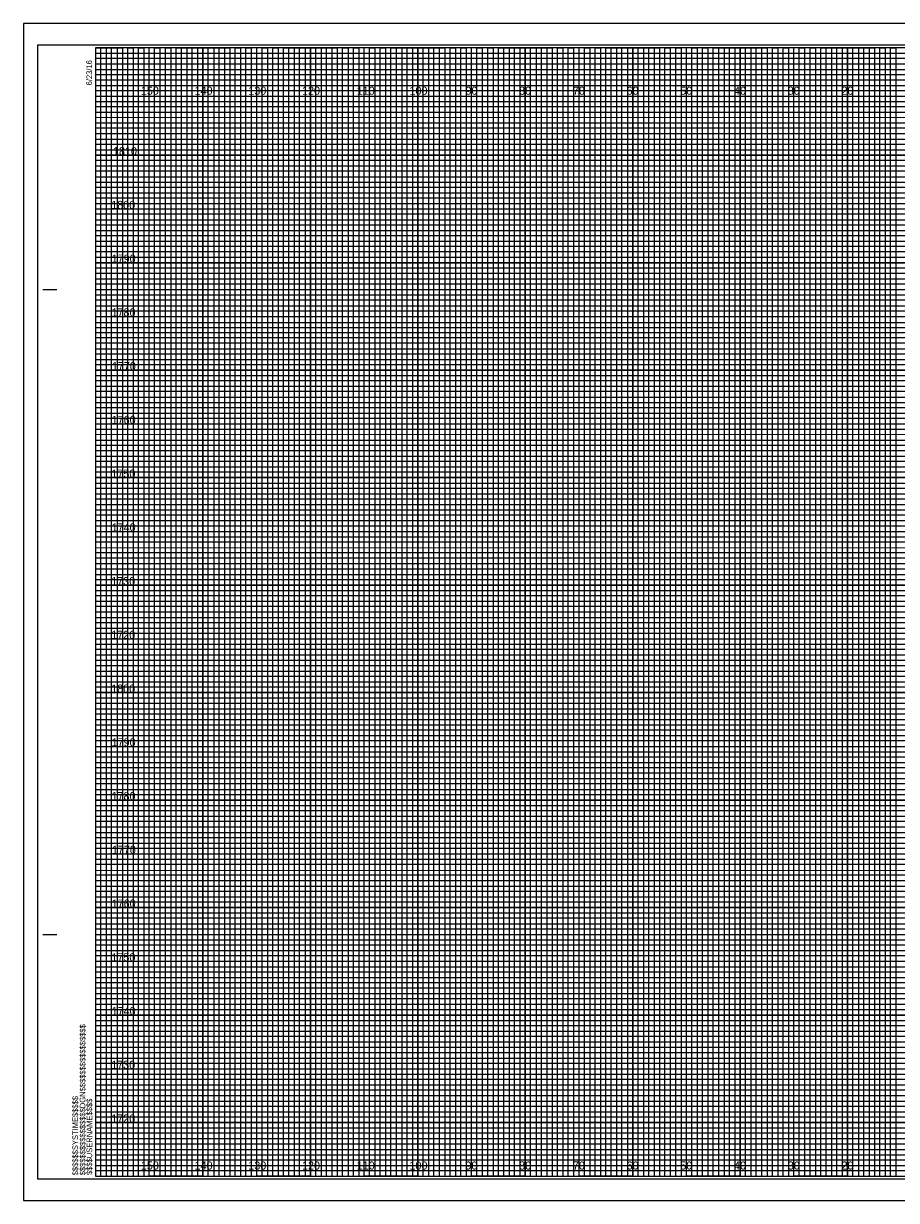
# Model space of a CAD drawing. Extents: x -13 to 323, y -5 to 874.
# Drawn here: x -13.4 to 149.1, y 655.5 to 874.5 of the extents above; entities that cross this region are included whole.
import ezdxf

# ---------------------------------------------------------------- set-up
doc = ezdxf.new("R2010")
doc.units = 0
for name, color, linetype in [('Prop XS DDE', 7, 'Continuous'), ('Prop XS DDE Elevations', 7, 'Continuous'), ('Prop XS DDE Slope Text', 7, 'Continuous'), ('Prop XS Gore Control Minimum', 7, 'Continuous'), ('Prop XS Shoulder Borrow Shape', 7, 'Continuous'), ('Raster_Level_0', 7, 'Continuous'), ('Scratch_Level_3', 7, 'Continuous'), ('Sheet Cutting Line CELL', 7, 'Continuous'), ('Sheet DOT Grid CELL', 7, 'Continuous'), ('Sheet Plot Border Inside CELL', 7, 'Continuous'), ('Sheet Plot Border Outside CELL', 7, 'Continuous')]:
    doc.layers.add(name, color=color, linetype=linetype)

msp = doc.modelspace()

# ---------------------------------------------------------------- linework, layer by layer
at = {"layer": 'Prop XS DDE'}
for p, q in [((0, 869), (260, 869)), ((260, 867.98), (0, 867.98)), ((0, 867.98), (0, 867)), ((0, 867), (260, 867)), ((260, 865.89), (0, 865.89)), ((0, 865.89), (0, 864)), ((0, 864), (320, 864))]:
    msp.add_line(p, q, dxfattribs=at)
for points in [[(0, 863), (270, 863), (320, 863), (320, 862), (0, 862)], [(0, 861), (320, 861), (320, 859), (0, 859)], [(0, 858), (320, 858), (320, 857), (0, 856.98)], [(0, 856), (320, 856), (320, 854), (0, 854)], [(0, 853), (320, 853), (320, 852), (0, 852)], [(0, 851), (320, 851), (320, 849), (0, 849)], [(0, 848), (320, 848), (320, 847), (0, 847)], [(0, 846), (320, 846), (320, 844), (0, 844)], [(0, 843), (320, 843), (320, 842), (0, 842)], [(0, 841), (320, 841), (320, 839), (0, 839)], [(0, 838), (320, 838), (320, 837), (0, 837)], [(0, 836), (320, 836), (320, 833.95), (320, 833), (320, 832), (0, 832)], [(0, 834), (320, 834), (320, 833), (0, 833)], [(0, 831), (320, 831), (320, 829), (0, 829.03)], [(0, 829.03), (320, 829), (320, 828), (0, 828)], [(0, 827), (320, 827), (320, 826), (0, 826)], [(0, 824), (320, 824), (320, 823), (0, 823)], [(0, 822), (320, 822), (320, 821), (0, 821)], [(-0.07, 818.89), (320, 818.89), (320, 817.88), (-0.07, 817.88)], [(0, 817), (320, 817), (320, 816), (0, 816)], [(0, 814), (320, 814), (320, 813), (0, 813)], [(0, 812), (320, 812), (320, 811), (0, 811)], [(0, 809), (320, 809), (320, 808), (0, 808)], [(0, 807), (320, 807), (320, 806), (0, 806)], [(0, 804), (320, 804), (320, 803), (0, 803)], [(0, 802), (320, 802), (320, 801), (0, 801)], [(0, 799), (320, 799), (319.99, 797.98), (0, 798)], [(0, 797), (320, 797), (320, 796), (0, 796)], [(0, 794), (320, 794), (320, 793), (0, 793)], [(0, 792), (320, 792), (320, 791), (0, 791)], [(0, 789), (320, 789), (320, 788), (0, 788)], [(0, 787), (320, 787), (320, 786), (0, 786)], [(0, 784), (320, 784), (320, 783), (0, 783)], [(0, 782), (320, 782), (320, 781), (0, 781)], [(0, 779), (320, 779), (320, 778), (0, 778)], [(0, 776.99), (320.07, 776.91), (320, 776), (0, 776)], [(0, 774), (320, 774), (320, 773), (0, 773)], [(0, 772), (320, 772), (320, 771), (0, 771)], [(0, 769), (320, 769), (320, 768), (0, 768)], [(0, 767), (320, 767), (320, 766), (0, 766)], [(0, 764), (320, 764), (320, 763), (0, 763)], [(0, 762), (320, 762), (320, 761), (0, 761)], [(0, 759), (320, 759), (320, 758), (0, 758)], [(0, 757), (320, 757), (320, 756), (0, 756)], [(0, 754), (320, 754), (320, 753), (0, 753)], [(0, 752), (320, 752), (320, 751), (0, 751)], [(0, 749), (320, 749), (320, 748), (0, 748)], [(0, 747), (320, 747), (320, 746), (0, 746)], [(0, 744), (320, 744), (320, 743), (0, 743)], [(0, 742), (320, 742), (320, 741), (0, 741)], [(0, 739), (320, 739), (319.99, 737.98), (0, 738)], [(0, 737), (320, 737), (320, 736), (0, 736)], [(0, 734), (320, 734), (320, 733), (0, 733)], [(0, 732), (320, 732), (320, 731), (0, 731)], [(0, 729), (320, 729), (320, 728), (0, 728)], [(0, 727), (320, 727), (320, 726), (0, 726)], [(0, 724), (320, 724), (320, 723), (0, 723)], [(0, 722), (320, 722), (320, 721), (0, 721)], [(0, 719), (320, 719), (320, 718), (0, 718)], [(0, 716.99), (320.07, 716.91), (320, 716), (0, 716)], [(0, 714), (320, 714), (320, 713), (0, 713)], [(0, 712), (320, 712), (320, 711), (0, 711)], [(0, 709), (320, 709), (320, 708), (0, 708)], [(0, 707), (320, 707), (320, 706), (0, 706)], [(0, 704), (320, 704), (320, 703), (0, 703)], [(0, 702), (320, 702), (320, 701), (0, 701)], [(0, 699), (320, 699), (320, 698), (0, 698)], [(0, 697), (320, 697), (320, 696), (0, 696)], [(0, 694), (320, 694), (320, 693), (0, 693)], [(0, 692), (320, 692), (320, 691), (0, 691)], [(0, 689), (320, 689), (320, 688), (0, 688)], [(0, 687), (320, 687), (320, 686), (0, 686)], [(0, 684), (320, 684), (320, 683), (0, 683)], [(0, 682), (320, 682), (320, 681), (0, 681)], [(0, 679), (320, 679), (320, 678), (0, 678)], [(0, 677), (320, 677), (320, 676), (0, 676)], [(0, 674), (320, 674), (320, 673), (0, 673)], [(0, 672), (320, 672), (320, 671), (0, 671)], [(0, 669), (320, 669), (320, 668), (0, 668)], [(0, 667), (320, 667), (320, 666), (0, 666)], [(0, 664), (320, 664), (320, 663), (0, 663)], [(0, 662), (320, 662), (320, 661), (0, 661)]]:
    msp.add_lwpolyline(points, dxfattribs=at)
at = {"layer": 'Prop XS DDE Elevations'}
for points in [[(0, 660), (1, 660), (1, 870), (2, 870), (2, 660)], [(2, 660), (3, 660), (3, 870), (4, 870), (4, 660)], [(5, 660), (6, 660), (6, 870), (7, 870), (7, 660)], [(7, 660), (8, 660), (8, 870), (9, 870), (9, 660)], [(10, 660), (11, 660), (11, 870), (12, 870), (12, 660)], [(12, 660), (13, 660), (13, 870), (14, 870), (14, 660)], [(15, 660), (16, 660), (16, 870), (17, 870), (17, 660)], [(17, 660), (18, 660), (18, 870), (19, 870), (19, 660)], [(20, 660), (21, 660), (21, 870), (22, 870), (22, 660)], [(22, 660), (23, 660), (23, 870), (24, 870), (24, 660)], [(25, 660), (26, 660), (26, 870), (27, 870), (27, 660)], [(27, 660), (28, 660), (28, 870), (29, 870), (29, 660)], [(30, 660), (31, 660), (31, 870), (32, 870), (32, 660)], [(32, 660), (33, 660), (33, 870), (34, 870), (34, 660)], [(35, 660), (36, 660), (36, 870), (37, 870), (37, 660)], [(37, 660), (38, 660), (38, 870), (39, 870), (39, 660)], [(40, 660), (41, 660), (41, 870), (42, 870), (42, 660)], [(42, 660), (43, 660), (43, 870), (44, 870), (44, 660)], [(45, 660), (46, 660), (46, 870), (47, 870), (47, 660)], [(47, 660), (48, 660), (48, 870), (49, 870), (49, 660)], [(50, 660), (51, 660), (51, 870), (52, 870), (52, 660)], [(52, 660), (53, 660), (53, 870), (54, 870), (54, 660)], [(55, 660), (56, 660), (56, 870), (57, 870), (57, 660)], [(57, 660), (58, 660), (58, 870), (59, 870), (59, 660)], [(60, 660), (61, 660), (61, 870), (62, 870), (62, 660)], [(62, 660), (63, 660), (63, 870), (64, 870), (64, 660)], [(65, 660), (66, 660), (66, 870), (67, 870), (67, 660)], [(67, 660), (68, 660), (68, 870), (69, 870), (69, 660)], [(70, 660), (71, 660), (71, 870), (72, 870), (72, 660)], [(72, 660), (73, 660), (73, 870), (74, 870), (74, 660)], [(75, 660), (76, 660), (76, 870), (77, 870), (77, 660)], [(77, 660), (78, 660), (78, 870), (79, 870), (79, 660)], [(80, 660), (81, 660), (81, 870), (82, 870), (82, 660)], [(82, 660), (83, 660), (83, 870), (84, 870), (84, 660)], [(85, 660), (86, 660), (86, 870), (87, 870), (87, 660)], [(87, 660), (88, 660), (88, 870), (89, 870), (89, 660)], [(90, 660), (91, 660), (91, 870), (92, 870), (92, 660)], [(92, 660), (93, 660), (93, 870), (94, 870), (94, 660)], [(95, 660), (96, 660), (96, 870), (97, 870), (97, 660)], [(97, 660), (98, 660), (98, 870), (99, 870), (99, 660)], [(100, 660), (101, 660), (101, 870), (102, 870), (102, 660)], [(102, 660), (103, 660), (103, 870), (104, 870), (104, 660)], [(105, 660), (106, 660), (106, 870), (107, 870), (107, 660)], [(107, 660), (108, 660), (108, 870), (109, 870), (109, 660)], [(110, 660), (111, 660), (111, 870), (112, 870), (112, 660)], [(112, 660), (113, 660), (113, 870), (114, 870), (114, 660)], [(115, 660), (116, 660), (116, 870), (117, 870), (117, 660)], [(117, 660), (118, 660), (118, 870), (119, 870), (119, 660)], [(120, 660), (121, 660), (121, 870), (122, 870), (122, 660)], [(122, 660), (123, 660), (123, 870), (124, 870), (124, 660)], [(125, 660), (126, 660), (126, 870), (127, 870), (127, 660)], [(127, 660), (128, 660), (128, 870), (129, 870), (129, 660)], [(130, 660), (131, 660), (131, 870), (132, 870), (132, 660)], [(132, 660), (133, 660), (133, 870), (134, 870), (134, 660)], [(135, 660), (136, 660), (136, 870), (137, 870), (137, 660)], [(137, 660), (138, 660), (138, 870), (139, 870), (139, 660)], [(140, 660), (141, 660), (141, 870), (142, 870), (142, 660)], [(142, 660), (143, 660), (143, 870), (144, 870), (144, 660)], [(145, 660), (146, 660), (146, 870), (147, 870), (147, 660)], [(147, 660), (148, 660), (148, 870), (149, 870), (149, 660)]]:
    msp.add_lwpolyline(points, dxfattribs=at)
at = {"layer": 'Prop XS DDE Slope Text'}
for p, q in [((-9.8, 825), (-7.3, 825)), ((-9.7, 825), (-7.2, 825)), ((-9.8, 705), (-7.3, 705)), ((-9.7, 705), (-7.2, 705)), ((0, 660), (0, 660)), ((0, 660), (0, 660)), ((0, 660), (0, 660)), ((0, 660), (0, 660)), ((0, 660), (0, 660)), ((0, 660), (0, 660)), ((0, 660), (0, 660))]:
    msp.add_line(p, q, dxfattribs=at)
msp.add_lwpolyline([(320, 870), (0, 870), (0, 660), (320, 660)], close=True, dxfattribs=at)
at = {"layer": 'Prop XS Gore Control Minimum'}
for p, q in [((10, 870), (0, 870)), ((10, 660), (10, 870)), ((30, 870), (20, 870)), ((20, 870), (20, 660)), ((30, 660), (30, 870)), ((50, 870), (40, 870)), ((40, 870), (40, 660)), ((50, 660), (50, 870)), ((70, 870), (60, 870)), ((60, 870), (60, 660)), ((70, 660), (70, 870)), ((90, 870), (80, 870)), ((80, 870), (80, 660)), ((90, 660), (90, 870)), ((110, 870), (100, 870)), ((100, 870), (100, 660)), ((110, 660), (110, 870)), ((130, 870), (120, 870)), ((120, 870), (120, 660)), ((130, 660), (130, 870)), ((150, 870), (140, 870)), ((140, 870), (140, 660)), ((20, 660), (10, 660)), ((40, 660), (30, 660)), ((60, 660), (50, 660)), ((80, 660), (70, 660)), ((100, 660), (90, 660)), ((120, 660), (110, 660)), ((140, 660), (130, 660))]:
    msp.add_line(p, q, dxfattribs=at)
for points in [[(0, 860), (320, 860), (320, 850), (0, 850)], [(0, 840), (320, 840), (320, 830), (0, 830)], [(0, 820), (320, 820), (320, 810), (0, 810)], [(0, 800), (320, 800), (320, 790), (0, 790)], [(0, 780), (320, 780), (320, 770), (0, 770)], [(0, 760), (320, 760), (320, 750), (0, 750)], [(0, 740), (320, 740), (320, 730), (0, 730)], [(0, 720), (320, 720), (320, 710), (0, 710)], [(0, 700), (320, 700), (320, 690), (0, 690)], [(0, 680), (320, 680), (320, 670), (0, 670)]]:
    msp.add_lwpolyline(points, dxfattribs=at)
at = {"layer": 'Prop XS Shoulder Borrow Shape'}
for points in [[(0, 870), (5, 870), (5, 660), (15, 660), (15, 870), (25, 870), (25, 660), (35, 660), (35, 870), (45, 870), (45, 660), (55, 660), (55, 870), (65, 870), (65, 660), (75, 660), (75, 870), (85, 870), (85, 660), (95, 660), (95, 870), (105, 870), (105, 660), (115, 660), (115, 870), (125, 870), (125, 660), (135, 660), (135, 870), (145, 870), (145, 660), (155, 660)], [(0, 865), (275, 865)], [(0, 845), (320, 845), (320, 855), (0, 855)], [(0, 825), (320, 825), (320, 835), (0, 835)], [(0, 805), (320, 805), (320, 815), (0, 815)], [(0, 785), (320, 785), (320, 795), (0, 795)], [(0, 765), (320, 765), (320, 775), (0, 775)], [(0, 745), (320, 745), (320, 755), (0, 755)], [(0, 725), (320, 725), (320, 735), (0, 735)], [(0, 705), (320, 705), (320, 715), (0, 715)], [(0, 685), (320, 685), (320, 695), (0, 695)], [(0, 665), (320, 665), (320, 675), (0, 675)]]:
    msp.add_lwpolyline(points, dxfattribs=at)
at = {"layer": 'Sheet Cutting Line CELL'}
for p, q in [((323.3, 874.5), (-13.4, 874.5)), ((-13.4, 874.5), (-13.4, 655.5)), ((-13.4, 655.5), (323.3, 655.5))]:
    msp.add_line(p, q, dxfattribs=at)
at = {"layer": 'Sheet DOT Grid CELL'}
for p, q in [((10, 660), (10, 870)), ((20, 660), (20, 870)), ((30, 660), (30, 870)), ((40, 660), (40, 870)), ((50, 660), (50, 870)), ((60, 660), (60, 870)), ((70, 660), (70, 870)), ((80, 660), (80, 870)), ((90, 660), (90, 870)), ((100, 660), (100, 870)), ((110, 660), (110, 870)), ((120, 660), (120, 870)), ((130, 660), (130, 870)), ((140, 660), (140, 870)), ((0, 860), (320, 860)), ((0, 850), (320, 850)), ((0, 840), (320, 840)), ((0, 830), (320, 830)), ((0, 820), (320, 820)), ((0, 810), (320, 810)), ((0, 800), (320, 800)), ((0, 790), (320, 790)), ((0, 780), (320, 780)), ((0, 770), (320, 770)), ((0, 760), (320, 760)), ((0, 750), (320, 750)), ((0, 740), (320, 740)), ((0, 730), (320, 730)), ((0, 720), (320, 720)), ((0, 710), (320, 710)), ((0, 700), (320, 700)), ((0, 690), (320, 690)), ((0, 680), (320, 680)), ((0, 670), (320, 670))]:
    msp.add_line(p, q, dxfattribs=at)
at = {"layer": 'Sheet Plot Border Inside CELL'}
msp.add_lwpolyline([(-10.8, 659.5), (322.4, 659.5), (322.4, 870.5), (-10.8, 870.5)], close=True, dxfattribs=at)
at = {"layer": 'Sheet Plot Border Outside CELL'}
msp.add_lwpolyline([(-13.4, 655.5), (323.3, 655.5), (323.3, 874.5), (-13.4, 874.5)], close=True, dxfattribs=at)

# ---------------------------------------------------------------- texts
at = {"layer": 'Prop XS DDE Slope Text'}
for s, p in [('6/23/16', (-0.65, 863)), ('$$$$$$$$$$$$$$$$DGN$$$$$$$$$$$$$$$$', (-1.88, 660.18)), ('$$$$$$SYSTIME$$$$$', (-3.26, 660.18)), ('$$$$USERNAME$$$$', (-0.62, 660.23))]:
    msp.add_text(s, height=1.05, rotation=90, dxfattribs=at).set_placement(p)
at = {"layer": 'Raster_Level_0'}
for s, p in [('150', (8.44, 861.25)), ('140', (18.44, 861.25)), ('130', (28.44, 861.25)), ('120', (38.44, 861.25)), ('110', (48.62, 861.25)), ('100', (58.44, 861.25)), ('90', (68.86, 861.25)), ('80', (78.86, 861.25)), ('70', (88.86, 861.25)), ('60', (98.86, 861.25)), ('50', (108.86, 861.25)), ('40', (118.86, 861.25)), ('30', (128.86, 861.25)), ('20', (138.86, 861.25)), ('150', (8.44, 661.25)), ('140', (18.44, 661.25)), ('130', (28.44, 661.25)), ('120', (38.44, 661.25)), ('110', (48.62, 661.25)), ('100', (58.44, 661.25)), ('90', (68.86, 661.25)), ('80', (78.86, 661.25)), ('70', (88.86, 661.25)), ('60', (98.86, 661.25)), ('50', (108.86, 661.25)), ('40', (118.86, 661.25)), ('30', (128.86, 661.25)), ('20', (138.86, 661.25))]:
    msp.add_text(s, height=1.5, dxfattribs=at).set_placement(p)
at = {"layer": 'Scratch_Level_3'}
for s, p in [('1810', (3.25, 850)), ('1800', (2.92, 840)), ('1790', (3, 830)), ('1780', (2.98, 820)), ('1770', (3.04, 810)), ('1760', (3, 800)), ('1750', (2.96, 790)), ('1740', (3, 780)), ('1730', (2.92, 770)), ('1720', (2.93, 760)), ('1800', (2.92, 750)), ('1790', (3, 740)), ('1780', (2.98, 730)), ('1770', (3.04, 720)), ('1760', (3, 710)), ('1750', (2.96, 700)), ('1740', (3, 690)), ('1730', (2.92, 680)), ('1720', (2.93, 670))]:
    msp.add_text(s, height=1.5, dxfattribs=at).set_placement(p)

doc.saveas('drawing.dxf')
